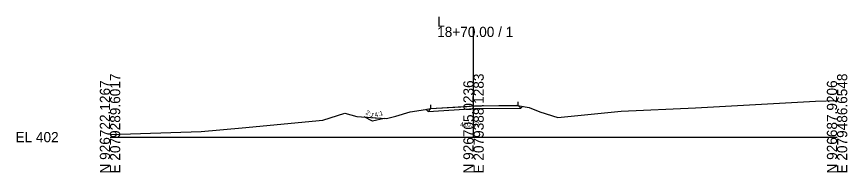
# Model space of a CAD drawing. Extents: x -26 to 10503, y -10 to 9546.
# Drawn here: x 3374.3 to 3602.8, y -9.7 to 33.1 of the extents above; entities that cross this region are included whole.
import ezdxf

# ---------------------------------------------------------------- set-up
doc = ezdxf.new("R2010")
doc.units = 0
for name, color, linetype in [('Default', 7, 'Continuous'), ('Exist Cross Section Cell', 7, 'Continuous'), ('Exist XS Center Line Elevation Label', 7, 'Continuous'), ('Exist XS Ground Line', 7, 'Continuous'), ('Old_Level_8', 7, 'Continuous'), ('Prop XS DDE', 7, 'Continuous'), ('Prop XS EOT Tick Mark', 7, 'Continuous'), ('Prop XS Finish Grade Pavement', 7, 'Continuous'), ('Prop XS Side Slope Text', 7, 'Continuous'), ('Prop XS Subgrade Earthwork', 7, 'Continuous')]:
    doc.layers.add(name, color=color, linetype=linetype)

msp = doc.modelspace()

# ---------------------------------------------------------------- linework, layer by layer
at = {"layer": 'Default'}
for points in [[(3475.45, 5.16), (3472.25, 4.36), (3469.87, 5.55), (3471.75, 5.41)], [(3469.87, 5.55), (3471.75, 5.41), (3475.45, 5.16), (3472.25, 4.36)]]:
    msp.add_lwpolyline(points, close=True, dxfattribs=at)
at = {"layer": 'Exist Cross Section Cell'}
for p, q in [((3500, 0), (3500, 30.34)), ((3400, 0), (3500, 0)), ((3500, 0), (3600, 0))]:
    msp.add_line(p, q, dxfattribs=at)
at = {"layer": 'Exist XS Ground Line'}
for p, q in [((3561.07, 8.09), (3594.04, 9.9)), ((3594.04, 9.9), (3600, 10.11)), ((3478.62, 5.73), (3482.53, 6.92)), ((3482.53, 6.92), (3486.75, 7.64)), ((3486.75, 7.64), (3488.16, 7.86)), ((3488.16, 7.86), (3498.18, 8.46)), ((3498.18, 8.46), (3500.29, 8.59)), ((3500.29, 8.59), (3502.23, 8.61)), ((3502.23, 8.61), (3511.7, 8.76)), ((3511.7, 8.76), (3512.65, 8.6)), ((3512.65, 8.6), (3515.31, 8.11)), ((3515.31, 8.11), (3518.25, 7)), ((3518.25, 7), (3523.2, 5.39)), ((3523.2, 5.39), (3540.62, 7.17)), ((3540.62, 7.17), (3561.07, 8.09)), ((3436.36, 2.56), (3458.52, 4.68)), ((3458.52, 4.68), (3464.58, 6.61)), ((3464.58, 6.61), (3467.93, 5.7)), ((3467.93, 5.7), (3471.75, 5.41)), ((3471.75, 5.41), (3476.06, 5.12)), ((3476.06, 5.12), (3478.62, 5.73)), ((3425.04, 1.52), (3436.36, 2.56)), ((3400, 0.74), (3425.04, 1.52))]:
    msp.add_line(p, q, dxfattribs=at)
at = {"layer": 'Old_Level_8'}
for p, q in [((3488.28, 7.87), (3487.48, 7.07)), ((3512.29, 8.71), (3513.03, 7.97))]:
    msp.add_line(p, q, dxfattribs=at)
at = {"layer": 'Prop XS DDE'}
for p, q in [((3472.25, 4.36), (3469.87, 5.55)), ((3475.45, 5.16), (3472.25, 4.36))]:
    msp.add_line(p, q, dxfattribs=at)
at = {"layer": 'Prop XS EOT Tick Mark'}
for p, q in [((3512.29, 8.71), (3512.29, 9.71)), ((3488.28, 7.87), (3488.28, 8.87))]:
    msp.add_line(p, q, dxfattribs=at)
at = {"layer": 'Prop XS Finish Grade Pavement'}
for p, q in [((3488.28, 7.87), (3500.29, 8.59)), ((3500.29, 8.59), (3512.29, 8.71))]:
    msp.add_line(p, q, dxfattribs=at)
at = {"layer": 'Prop XS Subgrade Earthwork'}
for p, q in [((3487.48, 7.07), (3486.89, 7.67)), ((3487.48, 7.07), (3500.33, 7.84)), ((3500.33, 7.84), (3513.03, 7.97)), ((3513.03, 7.97), (3513.5, 8.44))]:
    msp.add_line(p, q, dxfattribs=at)

# ---------------------------------------------------------------- texts
at = {"layer": 'Exist Cross Section Cell'}
for s, p in [('L', (3490, 30.34)), ('18+70.00 / 1', (3490, 27.54)), ('EL 402', (3374, -1.4))]:
    msp.add_text(s, height=2.8, dxfattribs=at).set_placement(p)
for s, p in [('E 2079289.6017', (3402.8, -10)), ('E 2079388.1283', (3502.8, -10)), ('E 2079486.6548', (3602.8, -10)), ('N 926722.1267', (3400, -10)), ('N 926705.0236', (3500, -10)), ('N 926687.9206', (3600, -10))]:
    msp.add_text(s, height=2.8, rotation=90, dxfattribs=at).set_placement(p)
at = {"layer": 'Exist XS Center Line Elevation Label'}
msp.add_text('410.57', height=1.25, rotation=360, dxfattribs=at).set_placement((3496.33, 2.86))
at = {"layer": 'Prop XS Side Slope Text'}
for s, rotation, p in [('2:1', 333.4349, (3470.18, 6.37)), ('4:1', 15.4834, (3472.92, 5.47))]:
    msp.add_text(s, height=1.25, rotation=rotation, dxfattribs=at).set_placement(p)

doc.saveas('drawing.dxf')
